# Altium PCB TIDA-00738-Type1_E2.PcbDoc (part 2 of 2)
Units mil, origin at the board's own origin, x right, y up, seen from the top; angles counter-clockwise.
Board outline 4723.41 x 3650 mil, 4 copper layers (Top Layer, GND, PWR, Bottom Layer), stack 79.834 mil thick; 251 components, 112 nets, 616 pads, 221 vias.
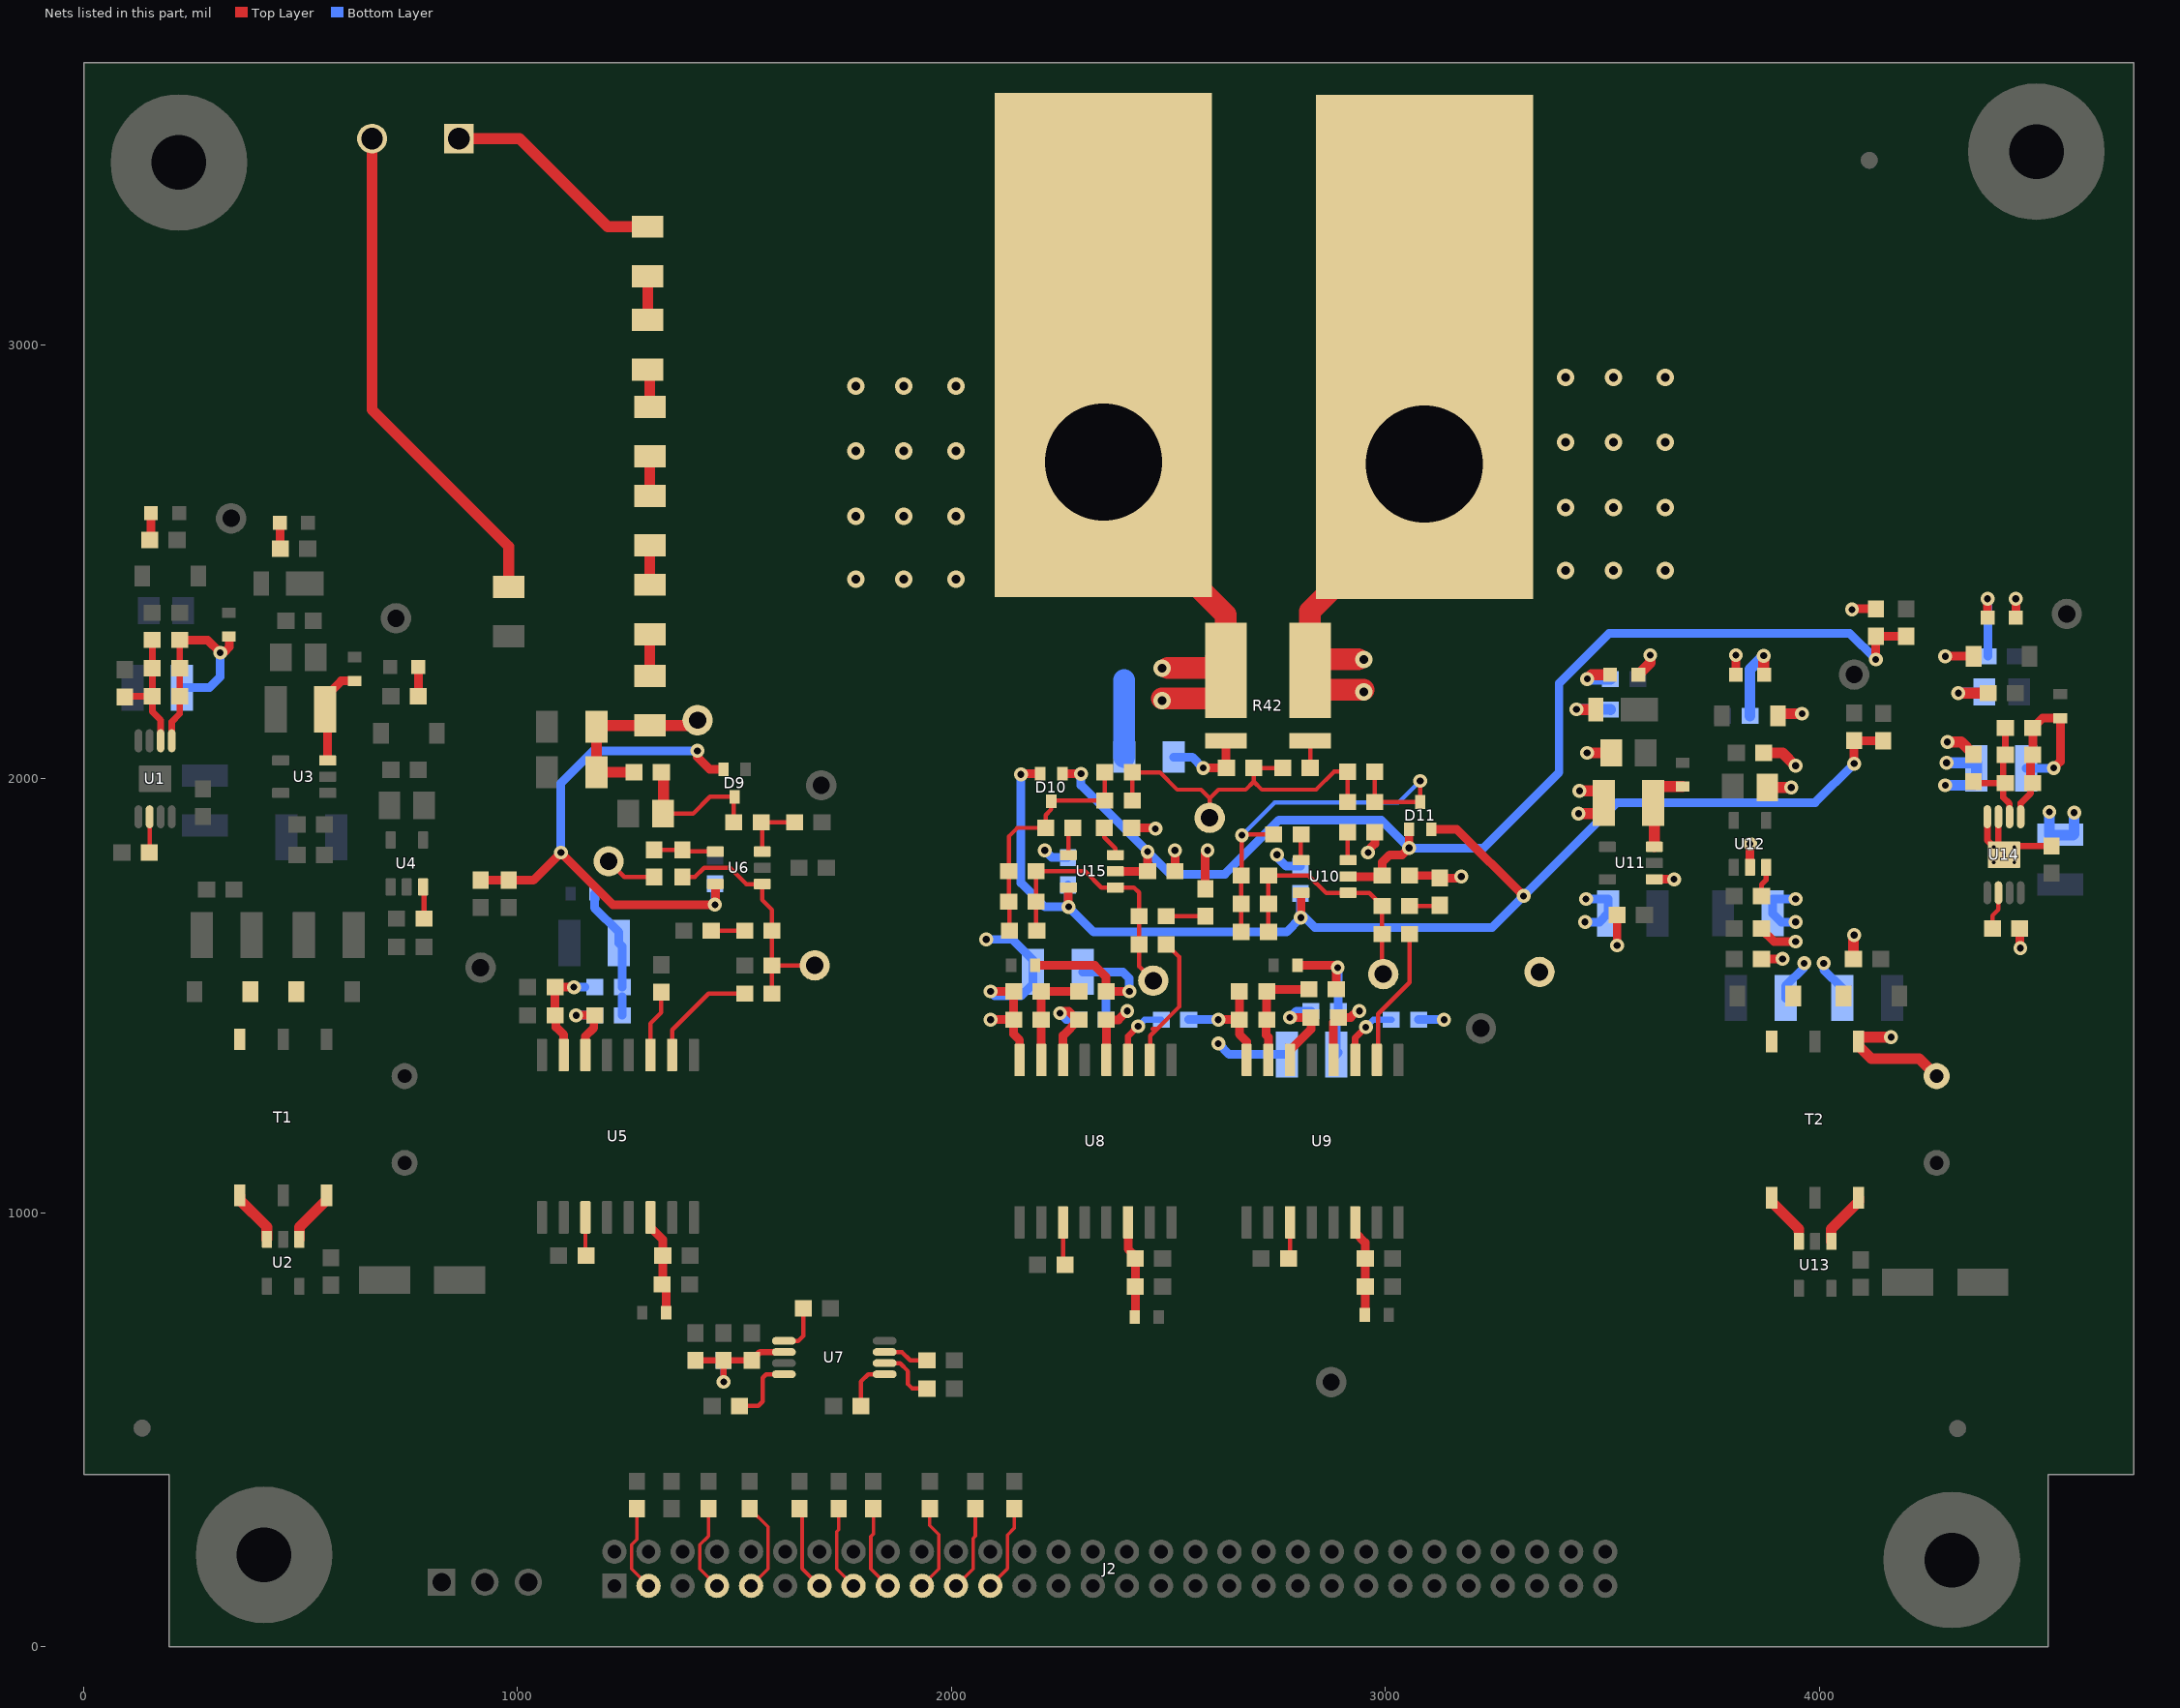
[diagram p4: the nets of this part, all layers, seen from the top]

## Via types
v1: diameter 32, hole 16, Top Layer to Bottom Layer, tented both sides, 183 vias
v2: diameter 40, hole 20, Top Layer to Bottom Layer, tented both sides, 28 vias
v3: diameter 19.68, hole 7.87, Top Layer to Bottom Layer, tented both sides, 10 vias

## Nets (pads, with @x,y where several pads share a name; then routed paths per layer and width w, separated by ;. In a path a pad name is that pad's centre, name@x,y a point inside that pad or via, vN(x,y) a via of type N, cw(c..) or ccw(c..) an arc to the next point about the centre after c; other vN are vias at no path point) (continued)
GND_USH: C30.2 C31.2 C32.2 C33.2 C36.1 C38.2 C39.2 C40.2 C41.2 C42.1 C46.2 C49.1 C50.1 C51.2 C52.1 C53.2 C54.2 C55.2 C56.1 C59.2 C60.2 C61.1 C63.2 C64.1 C65.1 C66.1 C67.1 C68.2 C69.1 C70.1 C71.2 C72.1 C73.1 C83.1 C84.1 D12.2 D13.1 D14.1 D15.2 D18.2 D19.1 R38.1 R42.2A R45.1 R50.1 R55.1 R57.2 R58.1 R79.1 T2.4 TP13.1 U8.4 U8.8 U9.4 U9.8 U11.1 U12.2 U14.3 U14.4 U14.9 | length 4972.9
  Top Layer w15: U14.4@4386.93,1912.6 4386.93,1858.07 4420,1825 v3(4425.31,1825) 4445.31,1845 4534.49,1845 C63.2@4535,1845.51 ; U14.9@4412.52,1842.72 U14.3@4412.52,1912.6
  Top Layer w20: v1(2090,1445) C31.2@2143.5,1445 ; v1(2090,1510) C30.2@2143.5,1510 C31.2@2143.5,1445 ; U8.8@2157,1352.01 2157,1398 2143.5,1411.5 C31.2@2143.5,1445 ; U8.4@2357.32,1351.69 U8.4@2357,1352.01 2357,1444.5 2384.5,1444.5 v1(2405,1465) ; R38.1@2415.02,1886.93 2468.07,1886.93 v1(2470,1885) ; C84.1@2515.02,1786.93 v1(2515,1835) ; v1(2580,2025) C40.2@2633.5,2025 2632,2026.5 R42.2A@2632,2087.5 ; C32.2@2585,1746.5 2585,1830 v1(2590,1835) ; v1(2615,1445) C39.2@2663.5,1445 ; C38.2@2663.5,1510 C39.2@2663.5,1445 ; U9.8@2680.32,1325 U9.8@2680.32,1352.01 2680.32,1394.68 2663.5,1411.5 C39.2@2663.5,1445 ; U9.4@2880.32,1352.01 2880.32,1438.82 C41.2@2891.5,1450 2920,1450 v1@2935,1465 ; v1(2960,1830) 2955,1830 2975.47,1850.47 R45.1@2975.47,1877.13 ; C36.1@3055.47,1777.13 3119.27,1777.13 C46.2@3124.97,1771.42 3171.42,1771.42 v1(3175,1775) ; v1@3460,1720 3462.09,1722.09 v1(3462.09,1722.91) ; v1(3533.82,1616.18) C51.2@3533.82,1685.98 ; U11.1@3619.45,1768.58 v1(3665,1768.58) ; D14.1@3807.52,2240 v1(3807.52,2285) ; U12.2@3840,1795.87 v1(3840,1850) ; C54.2@3866.5,1585 v1(3915,1585) ; C53.2@3866.5,1655 3866.5,1653.5 3895,1625 v1(3945,1625) ; v1(4075,2390) 4076.5,2391.5 R79.1@4130,2391.5 ; v1(4290.02,2282.27) D19.1@4355.55,2282.27 ; D18.2@4452.5,2371.28 v1(4452.54,2414.79) ; C61.1@4461.5,1655 4461.5,1611.5 v1(4462.99,1610)
  Top Layer w25: v1(3440,2160) 3440.31,2159.68 D12.2@3484.8,2159.68 ; v1(3445,1920) 3495,1920 3502.91,1927.91 C49.1@3502.91,1944.68 3502.91,1972.09 v1(3447.09,1972.09) ; v1(3464.69,2059.68) C50.1@3520,2059.68 ; D13.1@3582.48,2239.68 3610,2267.2 v1(3610,2285) ; C55.2@3871.5,2060 3915,2060 v1(3945,2030) ; C52.1@3890,1970 C52.1@3880,1980 v1(3935,1980) ; D15.2@3909.47,2145 3914.47,2150 v1(3960,2150) ; C56.1@4077.52,1585 C56.1@4078.5,1585 4078.5,1638.5 v1(4080,1640) ; v1(4165,1404.84) 4100,1404.84 T2.4@4090,1394.84 4090,1385 4120,1355 4230,1355 C59.2@4270,1315 ; v1(4293.02,2036.98) v1@4295,2035 ; v1(4295,2085) 4326.5,2085 R50.1@4355,2056.5 ; v1(4320.02,2197.27) C60.2@4388.52,2197.27
  Bottom Layer w20: v1(2080,1630) 2140,1630 2187.91,1582.09 C73.1@2187.91,1555 2187.91,1527.91 2160,1500 2100,1500 v1(2090,1510) ; v1(2215,1835) 2231.57,1818.43 C83.1@2268.53,1818.43 ; v1(2405,1465) v1@2410,1465 ; R57.2@2512.09,2050 2555,2050 v1(2580,2025) ; R58.1@2546.5,1445 v1(2615,1445) ; v1(2615,1390) 2640,1365 C72.1@2772.91,1365 ; v1(2750,1825) 2750,1820 2771.38,1798.62 C42.1@2803.97,1798.62 ; R55.1@3076.5,1445 v1(3135,1445) ; v1(3460,1670) 3493.23,1670 C70.1@3512.91,1689.68 3512.91,1722.91 v1(3462.09,1722.91) ; C68.2@3922.09,1495 3922.09,1522.61 3965,1565.52 v1(3965,1575) ; v1(3945,1670) 3912.09,1670 C69.1@3892.09,1690 3892.09,1722.91 v1(3945,1722.91) ; v1(4010,1575) 4010,1560 4052.91,1517.09 C67.1@4052.91,1495
  Bottom Layer w25: v1(3440,2160) 3518.19,2160 C71.2@3518.5,2159.68 ; v1(4290,1985) 4353.5,1985 4361.98,1993.48 C65.1@4361.98,2024.02 4361.98,2036.98 v1(4293.02,2036.98) ; v1(4320.02,2197.27) 4379.03,2197.27 C66.1@4380.02,2196.28 ; v1(4530,1923.86) 4530,1870 4583.86,1870 4586.93,1873.07 v1(4586.93,1921.93)
  other v1: 2940,1465
  other v3: 4401.69,1807.28 4448.94,1807.28 4401.69,1842.72 4448.94,1842.72
NetC1_2: C1.2 U1.6 | length 82.7
  Top Layer w10: C1.2@151.5,1830 152.2,1830.71 U1.6@152.2,1912.4
NetC3_1: C3.1 R1.2 R3.1 R77.1 U1.2 | length 304.5
  Top Layer w15: R1.2@95,2188.5 96.5,2190 R3.1@158.5,2190 ; C3.1@158.5,2320 R77.1@158.5,2255 R3.1@158.5,2190 ; U1.2@177.8,2087.6 177.8,2135.2 158.5,2154.5 R3.1@158.5,2190
NetC3_2: C3.2 C81.2 L1.1 R3.2 R77.2 U1.1 | length 534
  Top Layer w15: U1.1@203.39,2087.6 203.39,2131.39 221.5,2149.5 R3.2@221.5,2190 R77.2@221.5,2255 221.5,2307.5 C3.2@226.5,2312.5
  Top Layer w20: C3.2@221.5,2320 285.5,2320 v1(315,2290.5) ; v1@325,2292.5 336,2303.5 L1.1@336,2327.94
  Bottom Layer w20: C81.2@227.09,2210 290,2210 315,2235 v1(315,2290.5)
NetC7_2: C7.2 L2.1 U3.3 | length 232
  Top Layer w20: U3.3@562.61,2042.21 562.61,2154.48 C7.2@557.09,2160 557.09,2188.81 593.72,2225.44 L2.1@625,2225.44
NetC19_1: C19.1 C20.1 R60.2 U5.7 | length 234.1
  Top Layer w20: U5.7@1106.5,1363.5 1106.5,1410.24 1089,1427.73 1089,1452.5 C20.1@1086.5,1455 C19.1@1086.5,1520 v1(1130,1520)
  Bottom Layer w20: v1(1130,1520) 1155.82,1520
NetC21_1: C21.1 R61.2 U5.6 | length 187.6
  Top Layer w20: v1(1135,1455) C21.1@1178.5,1455 1176,1452.5 1176,1426 1156.5,1406.5 U5.6@1156.5,1363.5
  Bottom Layer w20: v1(1135,1455) R61.2@1178.5,1455
NetC22_2: C22.2 D9.3 R71.2 R81.1 | length 333.6
  Top Layer w10: C22.2@1335,1920 1405,1920 1443.5,1958.5 D9.3@1500,1958.5 1498.5,1957.01 R81.1@1498.5,1900
  Top Layer w25: C22.2@1336.5,1921.5 R71.2@1336.5,2015
NetC24_2: C24.2 C25.2 L5.1 U5.14 | length 235.7
  Top Layer w20: U5.14@1306.5,989.49 1306.5,966.5 1335,937.99 C25.2@1335,901.5 1335,836.5 C24.2@1333.5,835 1342.56,825.95 L5.1@1342.56,770
NetC26_1: C26.1 C27.1 C74.1 L6.2 U7.6 | length 288.2
  Top Layer w15: L6.2@1410,659.96 C26.1@1475,659.96 ; v1(1475,610.46) C26.1@1475,659.96 ; U7.6@1613.86,679.25 1559.29,679.25 C27.1@1540,659.96 C26.1@1475,659.96
  Bottom Layer w15: v1(1475,610.46) 1475,637.28
NetC28_1: C28.1 R19.1 | length 77
  Top Layer w10: C28.1@1446.5,1650 R19.1@1523.5,1650
NetC30_1: C30.1 C31.1 R35.2 U8.7 | length 245.2
  Top Layer w20: U8.7@2207,1352.01 2207,1444.5 C31.1@2206.5,1445 C30.1@2206.5,1510 R35.2@2293.5,1510
NetC32_1: C32.1 R36.1 | length 92.2
  Top Layer w10: R36.1@2495.02,1683.54 2495.06,1683.5 C32.1@2585,1683.5 C32.1@2583.43,1681.93
NetC33_1: C33.1 R59.2 U8.6 | length 226.9
  Top Layer w10: U8.6@2257,1339.69 U8.6@2257,1352.01
  Top Layer w20: v1(2250,1460) 2250,1465 2270,1465 2290,1445 C33.1@2293.5,1445 2257,1408.5 U8.6@2257,1352.01
  Bottom Layer w20: v1(2250,1460) 2265,1445 R59.2@2293.5,1445
NetC34_2: C34.2 C35.2 L9.1 U8.14 | length 207.5
  Top Layer w20: U8.14@2407,965.68 2407,917 C34.2@2423.5,900.5 ; L9.1@2422.44,760 2423.5,761.06 C35.2@2423.5,830 C34.2@2423.5,895
NetC37_1: C37.1 R36.2 R40.2 R66.2 R68.1 TP15.1 U15.1 | length 611.5
  Top Layer w10: C37.1@2196.5,1650 2195.02,1651.47 R40.2@2195.02,1716.93 R66.2@2195.02,1786.93 2308.07,1786.93 2345.47,1749.53 U15.1@2377.66,1749.53 2420.47,1749.53 2432.03,1737.97 R36.2@2432.03,1683.54 R68.1@2432.03,1618.54 2432.03,1567.97 TP15.1@2465,1535
NetC37_2: C37.2 D10.3 R37.2 R39.1 R40.1 R66.1 R67.2 | length 567
  Top Layer w10: C37.2@2133.5,1650 2133.5,1715.45 R40.1@2132.03,1716.93 R66.1@2132.03,1786.93 2132.03,1867.03 2151.93,1886.93 R39.1@2217.03,1886.93 2217.03,1916.7 2230,1929.67 D10.3@2230,1948.5 2231.5,1950 R67.2@2353.5,1950 R37.2@2353.5,2015
NetC38_1: C38.1 C39.1 R43.2 U9.7 | length 267
  Top Layer w20: U9.7@2730.32,1352.01 2730.32,1404.68 2725,1410 2725,1443.5 C39.1@2726.5,1445 C38.1@2726.5,1510 2731.5,1515 R43.2@2823.5,1515 R43.2@2818.5,1510
NetC41_1: C41.1 R56.2 U9.6 | length 221.2
  Top Layer w20: v1(2780,1450) C41.1@2828.5,1450 2828.5,1422.87 2780.32,1374.68 U9.6@2780.32,1352.01
  Bottom Layer w20: v1(2780,1450) 2795,1465 R56.2@2828.5,1465
NetC43_2: C43.2 C44.2 L14.1 U9.14 | length 223
  Top Layer w20: U9.14@2930.32,977.99 2930.32,954.68 2953.5,931.5 C43.2@2953.5,895 C44.2@2953.5,830 2953.5,766.06 L14.1@2952.44,765
NetC45_1: C45.1 R47.2 R48.2 R63.2 R65.1 TP12.1 U10.1 | length 579.2
  Top Layer w10: R63.2@2730.47,1647.13 R47.2@2730.47,1712.13 C45.1@2730.47,1777.13 2822.87,1777.13 2863.35,1736.65 2962.95,1736.65 R48.2@2992.48,1707.13 R65.1@2992.48,1642.13 2992.48,1552.52 TP12.1@2995,1550
NetC45_2: C45.2 D11.3 R44.2 R46.1 R47.1 R63.1 R64.2 | length 987.5
  Top Layer w10: R63.1@2667.48,1647.13 R47.1@2667.48,1712.13 C45.2@2667.48,1777.13 2669.25,1778.9 v1(2669.25,1870) 2667.13,1872.13 R46.1@2742.48,1872.13 ; R44.2@2975.47,2016.46 R64.2@2975.47,1946.46 R64.2@2975.47,1946.46 D11.3@3080,1946.5 v1(3080,1995)
  Bottom Layer w10: v1(2669.25,1870) 2744.25,1945 3030,1945 v1(3080,1995)
NetC46_1: C46.1 R48.1 | length 70
  Top Layer w10: R48.1@3055.47,1707.13 3123.67,1707.13 C46.1@3124.97,1708.43
NetC49_2: C49.2 L15.1 U11.3 | length 152.2
  Top Layer w25: C49.2@3617.09,1944.68 3619.45,1942.32 U11.3@3619.45,1843.39 ; C49.2@3635.07,1982.13 L15.1@3685,1982.13
NetC61_2: C61.2 U14.6 | length 88.2
  Top Layer w10: C61.2@4398.5,1655 4398.5,1684.7 4412.52,1698.72 U14.6@4412.52,1737.4
NetC62_1: C62.1 R50.2 R51.1 R69.1 U14.2 | length 285.7
  Top Layer w15: R50.2@4355,1993.5 4358.5,1990 R51.1@4423.5,1990 ; R69.1@4423.5,2060 R51.1@4423.5,1990 ; R69.1@4428.5,2055 C62.1@4428.5,2117.25 ; U14.2@4438.11,1912.6 4438.11,1942.35 4423.5,1956.95 R51.1@4423.5,1990
NetC62_2: C62.2 C65.2 L16.1 R51.2 R69.2 U14.1 | length 477.1
  Top Layer w15: U14.1@4463.7,1912.6 4463.7,1943.7 4486.5,1966.5 R51.2@4486.5,1990
  Top Layer w20: R51.2@4486.5,1990 R69.2@4486.5,2060 ; R69.2@4491.5,2055 4491.5,2117.25 4513.95,2139.71 L16.1@4555.02,2139.71 4555.02,2040.02 v1(4540,2025)
  Bottom Layer w20: C65.2@4476.16,2024.02 4539.02,2024.02 v1(4540,2025)
NetC72_2: C72.2 L11.1 R43.1 R56.1 | length 354.6
  Top Layer w20: L11.1@2797.56,1570 2885,1570 v1(2890,1565) 2886.5,1561.5 R43.1@2886.5,1515
  Bottom Layer w20: v1(2890,1565) 2891.5,1563.5 R56.1@2891.5,1465 2887.09,1460.59 C72.2@2887.09,1365 C72.2@2891.5,1369.41
NetC73_2: C73.2 L8.1 R35.1 R59.1 | length 516.6
  Top Layer w20: L8.1@2192.56,1570 2330,1570 2356.5,1543.5 R35.1@2356.5,1510 v1(2410,1510)
  Bottom Layer w20: C73.2@2302.09,1555 2395,1555 2410,1540 v1(2410,1510) 2370,1510 2356.5,1496.5 R59.1@2356.5,1445
NetC76_2: C76.2 L17.1 R60.1 R61.1 | length 284.8
  Bottom Layer w20: L17.1@1177.56,1735 1177.56,1702.44 1233.58,1646.42 C76.2@1233.58,1621.5 1241.5,1613.58 R60.1@1241.5,1520 ; R61.1@1241.5,1455 1241.5,1498.3
NetD1_1: D1.1 R2.1 | length 63.2
  Top Layer w20: R2.1@152.5,2550.5 155.52,2553.52 D1.1@155.52,2612.5
NetD3_1: D3.1 D6.2 T1.6
NetD5_2: D5.2 R4.1 | length 62.5
  Top Layer w20: D5.2@447.52,2590 453.5,2584.02 R4.1@453.5,2530
NetD7_2: D7.2 R5.1 | length 68
  Top Layer w20: R5.1@771.5,2190 D7.2@771.48,2258
NetD13_2: D13.2 R54.1 | length 110.2
  Top Layer w25: v1(3465,2230) 3474.69,2239.68 D13.2@3517.52,2239.68
  Bottom Layer w25: v1(3465,2230) 3465.31,2229.68 R54.1@3518.5,2229.68
NetD14_2: D14.2 R53.1 | length 196.7
  Top Layer w25: v1(3871.5,2283.5) 3871.5,2243.98 3870,2242.48 D14.2@3872.48,2240
  Bottom Layer w25: R53.1@3840,2145 3840,2252.01 v1(3871.5,2283.5)
NetD16_2: D16.2 D17.1 T2.6
NetD18_1: D18.1 R52.1 | length 176.4
  Top Layer w20: D18.1@4387.54,2371.28 v1(4387.54,2414.75)
  Bottom Layer w20: v1(4387.54,2414.75) 4388.52,2413.76 R52.1@4388.52,2282.27
NetJ1_1: J1.1 R7.1 | length 519
  Top Layer w25: J1.1@865,3475 1005,3475 1207.91,3272.09 R7.1@1300,3272.09
NetJ2_3: J2.3 R12.2 | length 199
  Top Layer w8: R12.2@1275,318.5 1275,247.52 1263.01,235.52 1263.01,179.63 J2.3@1302.01,140.63
NetJ2_7: J2.7 R21.2 | length 202.1
  Top Layer w8: R21.2@1440,318.5 1440,255.04 1420.49,235.52 1420.49,179.63 J2.7@1459.49,140.63
NetJ2_9: J2.9 R23.2 | length 211.5
  Top Layer w8: R23.2@1535,318.5 1577.23,276.28 1577.23,179.63 J2.9@1538.23,140.63
NetJ2_13: J2.13 R24.2 | length 196.8
  Top Layer w8: R24.2@1650,318.5 1655.97,312.54 1655.97,180.37 J2.13@1695.71,140.63
NetJ2_15: J2.15 R27.2 | length 195.9
  Top Layer w8: R27.2@1740,318.5 1740,270 1735.45,265.45 1735.45,179.63 J2.15@1774.45,140.63
NetJ2_17: J2.17 R28.2 | length 196.4
  Top Layer w8: R28.2@1820,318.5 1820,260 1814.19,254.19 1814.19,179.63 J2.17@1853.19,140.63
NetJ2_19: J2.19 R31.2 | length 202.7
  Top Layer w8: J2.19@1931.93,140.63 1970.93,179.63 1970.93,259.07 1950,280 R31.2@1950,318.5
NetJ2_21: J2.21 R32.2 | length 196.2
  Top Layer w8: J2.21@2010.67,140.63 2049.67,179.63 2049.67,250 2055,255.33 R32.2@2055,318.5
NetJ2_23: J2.23 R34.2 | length 200.9
  Top Layer w8: J2.23@2089.41,140.63 2129.15,180.37 2129.15,257.89 2145,273.74 R34.2@2145,318.5
NetJ4_1: J4.1 R42.2 R57.1 | length 1041.7
  Top Layer w50: J4.1@2350,2730 2350,2660 2632,2378 R42.2@2632,2250 ; v2@2485,2185 R42.2@2615,2185 ; v2@2498,2255 2610,2255 R42.2@2610,2280
  Bottom Layer w50: R57.1@2397.91,2050 2397.91,2227.91
  other v2: 2485,2180 2485,2255 1780,2460 1890,2460 2010,2460 1780,2605 1890,2605 2010,2605 1780,2755 1890,2755 2010,2755 1780,2905 1890,2905 2010,2905
NetJ5_1: J5.1 R42.1 | length 851.4
  Top Layer w50: R42.1@2820,2205 v2@2950,2205 ; R42.1@2825,2300 2825,2275 v2@2937,2275 ; R42.1@2826,2250 2826,2386 2850,2410 3090,2650 J5.1@3090,2725
  other v2: 2950,2200 2950,2275 3415,2480 3525,2480 3645,2480 3415,2625 3525,2625 3645,2625 3415,2775 3525,2775 3645,2775 3415,2925 3525,2925 3645,2925
NetR6_1: R6.1 U4.3 | length 73.7
  Top Layer w12: U4.3@782.4,1750.87 784.5,1748.77 R6.1@784.5,1678
NetR7_2: R7.2 R13.1 | length 75.2
  Top Layer w25: R13.1@1297.91,3055 R13.1@1300,3057.09 1300,3129.32
NetR8_2: R8.2 R9.2 R17.2 R71.1 TP6.1 | length 430.5
  Top Layer w25: R71.1@1268.5,2015 R9.2@1182.09,2015 R8.2@1182.09,2120 1185,2122.91 R17.2@1305,2122.91 1402.91,2122.91 TP6.1@1415,2135
NetR10_1: R10.1 U5.11 | length 88.6
  Top Layer w10: R10.1@1151.5,902.99 1151.5,911.5 1156.5,916.5 U5.11@1156.5,989.49
NetR11_2: R11.2 U5.3 | length 155.4
  Top Layer w10: U5.3@1306.5,1363.5 1306.5,1436.5 1331.5,1461.5 R11.2@1331.5,1508.5
NetR13_2: R13.2 R14.1 | length 87.9
  Top Layer w25: R13.2@1300,2942.91 1305,2937.91 R14.1@1305,2857.09
NetR14_2: R14.2 R15.1 | length 90.8
  Top Layer w25: R15.1@1305,2652.09 R14.2@1305,2742.91
NetR15_2: R15.2 R16.1 | length 90.8
  Top Layer w25: R16.1@1305,2447.09 R15.2@1305,2537.91
NetR16_2: R16.2 R17.1 | length 95.8
  Top Layer w25: R17.1@1305,2237.09 R16.2@1305,2332.91
NetR19_2: R19.2 R20.2 R70.2 R80.1 TP7.1 U6.1 | length 568.9
  Top Layer w10: R70.2@1380,1773.5 1408.5,1773.5 1430,1795 1490,1795 1527.4,1757.6 U6.1@1564.13,1757.6 1564.13,1720.87 1586.5,1698.5 R19.2@1586.5,1650 R20.2@1586.5,1570 ; R80.1@1586.5,1505 R20.2@1586.5,1570 ; TP7.1@1685,1570 R20.2@1586.5,1570
NetR22_2: R22.2 U7.8 | length 168.2
  Top Layer w10: R22.2@1511.5,555 1555,555 1565,565 1565,620 1573.07,628.07 U7.8@1613.86,628.07 U7.8@1611.5,625.71
NetR25_2: R25.2 U7.5 | length 113
  Top Layer w10: U7.5@1613.86,704.84 1646.94,704.84 1658.5,716.4 R25.2@1658.5,780
NetR26_1: R26.1 U7.1 | length 118
  Top Layer w10: R26.1@1791.5,555 1791.5,611.5 1808.07,628.07 U7.1@1846.14,628.07
NetR29_2: R29.2 U7.3 | length 105.3
  Top Layer w10: U7.3@1846.14,679.25 1885.75,679.25 1905,660 R29.2@1943.5,660
NetR30_1: R30.1 U7.2 | length 139.2
  Top Layer w10: U7.2@1846.14,653.66 1881.34,653.66 1900,635 1900,605 1910,595 R30.1@1943.5,595
NetR33_1: R33.1 U8.11 | length 87.3
  Top Layer w10: R33.1@2255,891.5 2257,893.5 U8.11@2257,977.99
NetR38_2: R38.2 U15.3 | length 83.2
  Top Layer w10: R38.2@2345,1879.9 R38.2@2352.03,1886.93 2352.03,1864.94 2377.66,1839.31 U15.3@2377.66,1824.33
NetR39_2: R39.2 U15.4 | length 67
  Top Layer w10: U15.4@2269.39,1824.33 2269.39,1876.3 R39.2@2280.02,1886.93
NetR41_1: R41.1 U9.11 | length 86.5
  Top Layer w10: R41.1@2780.32,891.5 U9.11@2780.32,977.99
NetR42_1A: R42.1A R74.1 | length 62.7
  Top Layer w10: R42.1A@2826,2087.5 2826.5,2087 R74.1@2826.5,2025
NetR45_2: R45.2 U10.3 | length 65.9
  Top Layer w10: R45.2@2912.48,1877.13 2913.11,1876.5 U10.3@2913.11,1811.46
NetR46_2: R46.2 U10.4 | length 60.9
  Top Layer w10: U10.4@2804.84,1811.46 2804.84,1871.5 R46.2@2805.47,1872.13
NetR49_1: R49.1 U12.3 | length 75.4
  Top Layer w12: R49.1@3866.5,1730 3866.5,1756.5 3877.4,1767.4 U12.3@3877.4,1800.87
NetR55_2: R55.2 U9.3 | length 151.8
  Top Layer w15: U9.3@2930.32,1352.01 2930.32,1403.31 v1(2955,1427.99)
  Bottom Layer w15: v1(2955,1427.99) 2972.01,1445 R55.2@3013.5,1445
NetR58_2: R58.2 U8.3 | length 147.2
  Top Layer w15: U8.3@2407,1352.01 2407,1407 v1(2430,1430)
  Bottom Layer w15: v1(2430,1430) 2445,1445 R58.2@2483.5,1445
NetR65_2: R65.2 U9.2 | length 321.2
  Top Layer w10: U9.2@2980.32,1352.01 2983,1354.69 2983,1458 3055.47,1530.47 R65.2@3055.47,1642.13
NetR68_2: R68.2 U8.2 | length 317.3
  Top Layer w10: U8.2@2457,1352.01 2458,1353.01 2458,1408 2474,1424 ; 2464.03,1424 2474,1424 ; R68.2@2495.02,1618.54 2496.01,1618.54 2524.55,1590 2524.55,1474.55 2474,1424
NetR70_1: R70.1 R82.2 U6.4 | length 142.6
  Top Layer w10: R82.2@1315,1836.5 R70.1@1380,1836.5 1384.09,1832.4 U6.4@1455.87,1832.4
NetR80_2: R80.2 U5.2 | length 259.6
  Top Layer w10: U5.2@1356.5,1363.5 1356.5,1421.5 1440,1505 R80.2@1523.5,1505
NetR81_2: R81.2 R83.2 U6.3 | length 145.7
  Top Layer w10: U6.3@1564.13,1832.4 1564.13,1897.36 R81.2@1561.5,1900 R83.2@1638.5,1900
NetR82_1: R82.1 TP14.1 | length 120.1
  Top Layer w10: TP14.1@1210,1810 1246.5,1773.5 R82.1@1315,1773.5
NetT1_1: T1.1 U2.3 | length 126.8
  Top Layer w25: T1.1@360,1040 360,1030 422.6,967.4 U2.3@422.6,939.13
NetT1_3: T1.3 U2.1 | length 126.8
  Top Layer w25: U2.1@497.4,939.13 497.4,967.4 560,1030 T1.3@560,1040
NetT2_1: T2.1 U13.3 | length 103.9
  Top Layer w25: T2.1@3890,1035 3890,1025 3952.6,962.4 3952.6,956.98
NetT2_3: T2.3 U13.1 | length 126.8
  Top Layer w25: U13.1@4027.4,934.13 4027.4,962.4 4090,1025 T2.3@4090,1035
NEUTRAL: J1.2 R62.1 | length 1163.4
  Top Layer w25: J1.2@665,3475 665,2850 980,2535 R62.1@980,2442.09
SHUNT_H: C40.1 R37.1 R44.1 R64.1 R67.1 R74.2 TP9.1 | length 840.1
  Top Layer w10: R67.1@2416.5,1950 R37.1@2416.5,2015 2480,2015 2520,1975 2575,1975 2595,1955 ; TP9.1@2595,1910 2595,1955 ; R74.2@2763.5,2025 C40.1@2696.5,2025 2696.5,1993.5 ; R64.1@2912.48,1946.46 R44.1@2912.48,2016.46 2881.46,2016.46 2840,1975 2715,1975 2696.5,1993.5 ; 2595,1955 2615,1975 2677.99,1975 2696.5,1993.5
VAN+: C42.2 C83.2 D10.2 D11.2 R75.2 R76.2 U10.5 U15.5 | length 3035.4
  Top Layer w20: v1(2160,2010) 2161.5,2011.5 D10.2@2204.41,2011.5 ; U15.5@2269.39,1749.53 2269.39,1705.61 v1(2270,1705) ; v1(2805,1680) 2805.87,1680.87 U10.5@2805.87,1737.6 ; D11.2@3105.59,1883.5 3164.83,1883.5 v1(3318.33,1730) v1@3318.5,1730.17 ; v1(4080,2035) R75.2@4080,2088.5 4081,2087.5 R76.2@4147,2087.5 R76.2@4146,2088.5
  Bottom Layer w20: v1(2160,2010) 2160,1760 2215,1705 v1(2270,1705) ; C83.2@2268.53,1755.43 2268.53,1706.47 v1(2270,1705) ; v1@2803.97,1691.03 C42.2@2803.97,1735.63 ; v1(2805,1680) 2772.16,1647.16 2327.84,1647.16 v1(2270,1705) ; v1@2810,1685 2837.5,1657.5 3245.84,1657.5 v1(3318.33,1730) 3533.33,1945 3990,1945 v1(4080,2035)
VAN-: C36.2 C84.2 D10.1 D11.1 R78.2 R79.2 U10.2 U15.2 | length 2886.2
  Top Layer w20: D10.1@2255.59,2011.5 v1(2298.5,2011.5) ; U15.2@2377.66,1786.93 C84.2@2452.03,1786.93 v1(2452.03,1832.03) ; U10.2@2913.11,1774.05 2989.41,1774.05 C36.2@2992.48,1777.13 2992.48,1807.48 3010,1825 3038.82,1825 v1(3054.41,1840.59) D11.1@3054.41,1883.5 ; v1(4130,2275) R79.2@4130,2328.5 R78.2@4200,2328.5
  Bottom Layer w20: v1(2298.5,2011.5) 2298.5,1985.55 v1(2452.03,1832.03) 2504.06,1780 2630,1780 2755,1905 2990,1905 v1(3054.41,1840.59) 3225.59,1840.59 3400,2015 3400,2220 3515,2335 4070,2335 v1(4130,2275)
VANP+: C29.2 D9.2 R72.2 R73.2 U6.5 | length 1280.9
  Top Layer w20: R72.2@915,1766.5 R73.2@980,1766.5 1036.5,1766.5 v1(1100,1830) 1220,1710 v1(1455,1710) 1455.87,1710.87 U6.5@1455.87,1757.6 ; v1(1414.41,2064.41) 1414.41,2050.59 1443.5,2021.5 D9.2@1474.41,2021.5
  Bottom Layer w20: v1(1100,1830) 1100,1990 1174.41,2064.41 v1(1414.41,2064.41) ; v1(1455,1710) 1455,1735.82
pads on no net: FID1.1 FID2.1 FID3.1 FID4.1 FID5.1 FID6.1 H1.1 H2.1 H3.1 H4.1 J2.4 J2.6 J2.8 J2.10 J2.11 J2.12 J2.14 J2.16 J2.18 J2.20 J2.24 J2.25 J2.26 J2.27 J2.28 J2.29 J2.30 J2.31 J2.32 J2.33 J2.34 J2.35 J2.36 J2.37 J2.38 J2.41 J2.42 J2.43 J2.44 J2.45 J2.46 J2.47 J2.48 J2.49 J2.50 J2.51 J2.52 J2.53 J2.54 J2.55 J2.56 J2.57 J2.58 R24.1 R27.1 R32.1 R34.1 T1.5 T2.5 U1.7 U3.4 U3.5 U4.4 U5.1 U5.5 U5.10 U5.12 U5.15 U7.7 U8.1 U8.5 U8.10 U8.12 U8.15 U9.1 U9.5 U9.10 U9.12 U9.15 U11.4 U11.5 U12.4 U14.7

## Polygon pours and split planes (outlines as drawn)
+6V_PH on Top Layer "Top Layer-No Net" (solid, pour order 27): 720,1775 720,1720 740,1700 745,1695 745,1675 745,1490 730,1475 592.5,1475 580,1487.5 580,1730 575,1735 465,1735 405,1795 385,1815 385,1895 385,1920 395,1930 510,1930 515,1925 515,1795 520,1790 705,1790
-6V_PH on Top Layer "Top Layer-No Net" (solid, pour order 21): 270,1480 210,1480 200,1490 200,1925 210,1935 325,1935 335,1925 335,1805 300,1770 300,1635 300,1490 290,1480
NetD3_1 on Top Layer "Top Layer-No Net" (solid, remove dead copper, pour order 25): 360,1535 370,1545 500,1545 505,1540 505,1455 500,1450 395,1450 370,1425 370,1405 370,1380 365,1375 300,1375 295,1380 295,1420 360,1485
+6V_USH on Top Layer "Top Layer-No Net" (solid, remove dead copper, pour order 28): 3575,1720 3580,1725 3585,1730 3645,1730 3650,1730 3660,1740 3665,1745 3665,1790 3660,1795 3635,1795 3635,1815 3660,1815 3665,1820 3670,1825 3705,1825 3810,1825 3815,1820 3815,1778 3815,1775 3825,1765 3825,1690 3825,1575 3825,1470 3825,1450 3820,1445 3745,1445 3590,1445 3575,1460 3575,1720
NetD16_2 on Top Layer "Top Layer-No Net" (solid, remove dead copper, pour order 29): 3825,1375 3830,1370 3905,1370 3910,1375 3910,1415 3940,1445 4065,1445 4075,1455 4075,1535 4070,1540 3930,1540 3920,1530 3920,1485 3865,1430 3830,1430 3825,1425
-6V_USH on Top Layer "Top Layer-No Net" (solid, pour order 35): 4470,1770 4465,1765 4465,1710 4490,1710 4495,1705 4520,1680 4520,1670 4520,1595 4510,1585 4370,1585 4355,1600 4355,1750 4345,1760 4130,1760 4120,1750 4120,1555 4125,1550 4145,1550 4160,1535 4160,1470 4175,1455 4605,1455 4630,1480 4630,1790 4615,1805 4505,1805 4485,1785
NetJ4_1 on Top Layer "Bottom Layer-No Net 1" (solid, remove dead copper, pour order 20): 2600,2450 2600,2150 2590,2140 2585,2135 2450,2135 2370,2135 2360,2145 2360,2410 2350,2420 1755,2420 1735,2440 1735,2930 1755,2950 2095,2950 2105,2960 2105,3550 2120,3565 2585,3565 2595,3555
NetJ5_1 on Top Layer "Bottom Layer-No Net 1" (solid, remove dead copper, pour order 24): 2840,2470 2840,2145 2845,2140 3015,2140 3030,2155 3030,2399.29 3040.71,2410 3665,2410 3685,2430 3685,2980 3670,2995 3360,2995 3345,3010 3315,3040 3315,3265 3315,3545 3305,3555 2850,3555 2840,3545
GND_USH on GND "Top Layer-No Net" (solid, remove dead copper, pour order 32): 3945,1595 3950,1600 4000,1600 4015,1600 4020,1595 4025,1590 4025,1565 4025,1500 4025,1455 4050,1430 4170,1430 4185,1415 4185,1390 4185,1385 4175,1375 4170,1370 4050,1370 3960,1370 3945,1385 3945,1590
DGND on GND "Top Layer-No Net" (solid, remove dead copper, pour order 33): 50,825 50,950 75,975 325,975 535,975 710,1150 790,1150 915,1025 3750,1025 3800,975 4075,975 4250,1150 4475,1150 4650,975 4675,950 4675,800 4675,625 4650,600 4400,600 4175,600 4050,475 4000,425 4000,350 4000,75 3975,50 725,50 700,75 700,450 700,575 650,625 175,625 100,625 50,675
GND_USH on GND "Top Layer-No Net" (solid, remove dead copper, pour order 34): 2045,1980 2110,2045 3170,2045 3450,2325 3675,2325 3925,2325 4100,2500 4625,2500 4675,2450 4675,1775 4675,1475 4650,1450 4300,1450 4075,1450 4050,1475 4050,1570 4040,1580 3880,1580 3825,1525 3815,1515 3815,1450 3815,1440 3775,1400 3750,1375 3725,1350 3700,1325 2750,1325 2085,1325 2045,1365
GND_PH on GND "Top Layer-No Net" (solid, pour order 36): 695,1450 695,1385 685,1375 410,1375 400,1385 400,1685 405,1690 465,1690 470,1685 470,1465 480,1455 690,1455 695,1450
GND_PH on GND "Top Layer-No Net" (solid, pour order 23): 55,2635 55,2640 85,2670 515,2670 905,2280 1005,2280 1030,2255 1030,1970 1055,1945 1505,1945 1740,1945 1765,1920 1765,1345 1735,1315 935,1315 779.37,1470.63 594.37,1470.63 585,1480 585,1655 560,1680 290,1680 270,1660 270,1540 250,1520 90,1520 50,1560 50,2630
+3.3V_DVDD on PWR "Top Layer-No Net" (solid, remove dead copper, pour order 31): 800,75 3725,75 3750,100 3750,1000 3725,1025 850,1025 775,950 775,100
+5.0V_PH on PWR "Top Layer-No Net" (solid, remove dead copper, pour order 30): 475,2375 500,2400 675,2400 750,2400 775,2375 775,1898.49 884.66,1788.83 1745.99,1788.83 1765,1769.82 1765,1345 1745,1325 925,1325 475,1775
+5.0V_USH on PWR "Bottom Layer-No Net 1" (solid, remove dead copper, pour order 26): 2045,1617.97 2045,1365 2085,1325 3575,1325 4240,1990 4240,2287.28 4227.27,2300.02 4197.28,2330 3620,2330 3455,2330 3401.91,2276.91 3120,1995 2552.89,1995 2500,1942.11 2500,1850 2475,1825 2375,1825 2294.8,1744.8 2175,1625 2172.89,1622.89 2049.29,1622.89
NetJ4_1 on Bottom Layer "Bottom Layer-No Net 1" (solid, remove dead copper, pour order 19): 2600,2450 2600,2150 2590,2140 2585,2135 2450,2135 2370,2135 2360,2145 2360,2410 2350,2420 1755,2420 1735,2440 1735,2930 1755,2950 2095,2950 2105,2960 2105,3550 2120,3565 2585,3565 2595,3555
NetJ5_1 on Bottom Layer "Bottom Layer-No Net 1" (solid, remove dead copper, pour order 22): 2840,2470 2840,2145 2845,2140 3015,2140 3030,2155 3030,2399.29 3040.71,2410 3665,2410 3685,2430 3685,2980 3670,2995 3360,2995 3345,3010 3315,3040 3315,3265 3315,3545 3305,3555 2850,3555 2840,3545

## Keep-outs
Keep-Out Layer:
  lines w10: 25,421.7 220.15,421.7 221.85,420 221.85,25 4502,25 4502,393 4502,417 4506.7,421.7 4700,421.7 4700,3630 25,3630 25,421.7
  text ".Layer_Name" at 552,-833.49 h60

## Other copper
Top Layer:
  pour cut-out: 2917.5,2430 2912.5,2435 2777.5,2435 2777.5,2205 2797.5,2185 2907.5,2185 2917.5,2195
  pour cut-out: 2537.5,2430 2542.5,2435 2677.5,2435 2677.5,2205 2657.5,2185 2547.5,2185 2537.5,2195
  text ".Layer_Name" at 552,-833.49 h60
GND:
  text ".Layer_Name" at 552,-833.49 h60
PWR:
  text ".Layer_Name" at 544,-841.49 h60
Bottom Layer:
  text ".Layer_Name" at 552,-833.49 h60

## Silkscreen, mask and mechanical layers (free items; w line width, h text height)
Top Overlay:
  circle w6: c1605,1745 r9.37
  circle w6: c590,1940 r7.07
  circle w6: c1405,1420 r6.4
  circle w6: c535,938 r5
  circle w6: c3640,1730 r7.07
  circle w6: c2505,1410 r7.81
  circle w6: c1850,586 r8.06
  circle w6: c4500,1910 r5
  circle w6: c4060,960 r5
  circle w6: c3030,1405 r5
  circle w6: c203.39,2131.39 r9.19
  circle w10: c660,1750 r10
  circle w10: c2380,1710 r5
  circle w10: c2940,1705 r5
  circle w10: c3755,1800 r7.07
  lines w6: 638,785 658,785 ; 648,772 648,798 ; 660,1089 ccw(c740,1089) 820,1089 ; 660,1090 660,1340 cw(c740,1340) 820,1340 820,1090 ; 798,2259 813,2259 ; 812,2249 812,2269 ; 828,2258 829,2259 844,2259 ; 828,2264 828,2274 813,2259 ; 828,2269 828,2244 813,2259 ; 2295,2105 2215,2105 2215,2255 2300,2255 2315,2255 2315,2140 ; 2305,2040 2305,2060 2325,2060 ; 2310,1930 2310,1990 ; 2350,2055 2320,2085 2320,2115 ; 2361.97,1855 2366.97,1850 2405,1850 ; 2365,2060 2455,2060 2455,1905 ; 2615,1640 2620,1645 2630,1645 ; 2758.96,1684.93 2765.07,1684.93 2780,1670 2780,1655 2790,1645 ; 2870,1850 2870,2045 2890,2065 2970,2065 ; 2985,2055 3050,2120 ; 3015,1870 3015,2060 ; 3055,2140 3055,2245 3175,2245 3175,2100 3065,2100 ; 3125,1570 3105,1570 3095,1580 3095,1600 ; 4152,785 4172,785 ; 4162,772 4162,798 ; 4190,1090 ccw(c4270,1090) 4350,1090 ; 4190,1091 4190,1341 cw(c4270,1341) 4350,1341 4350,1091 ; 2320,2115 2310,2105 2330,2105 2320,2115 ; 3050,2120 3030,2120 3045,2105 3050,2100 3050,2120 ; 3095,1600 3085,1590 3105,1590 3095,1600 ; 3135,1500 3135,1640 3185,1640 3245,1640 3245,1500 3135,1500
  text "TIDA-00738-Type1-E2" at 3460,3090 h60
  text "HIGH VOLTAGE" at 724,2862 h40
  text ".Layer_Name" at 552,-833.49 h60
Bottom Overlay:
  text ".Layer_Name" at 552,-833.49 h60
Top Paste:
  text ".Layer_Name" at 552,-833.49 h60
Bottom Paste:
  text ".Layer_Name" at 552,-833.49 h60
Top Solder:
  rectangle: 1735,2425 2323.46,2950
  rectangle: 3150,2415 3685,2980
  text ".Layer_Name" at 552,-833.49 h60
  text ".Layer_Name" at 552,-833.49 h60
Bottom Solder:
  text ".Layer_Name" at 552,-833.49 h60
Drill Guide:
  text ".Layer_Name" at 552,-833.49 h60
M1 Board Outline:
  the board outline again, w10
M2 Board Dimensions:
  rectangle: -25.5,-260.5 99.5,-135.5
  rectangle: 99.5,-385.5 474.5,-260.5
  lines w7: -25.5,-260.5 974.5,-260.5 ; 99.5,-385.5 99.5,-135.5 ; 224.5,-385.5 224.5,-135.5 ; 474.5,-385.5 474.5,-135.5 ; 724.5,-385.5 724.5,-135.5 ; -25.5,-385.5 974.5,-385.5 974.5,-135.5 -25.5,-135.5 -25.5,-385.5
  lines w10: -25.5,-450.5 -25.5,-430.5 ; 34.5,-460.5 -25.5,-440.5 ; 34.5,-420.5 -25.5,-440.5 ; 198.58,-440.5 -25.5,-440.5 ; 750.42,-440.5 974.5,-440.5 ; 914.5,-460.5 974.5,-440.5 ; 914.5,-420.5 974.5,-440.5 ; 974.5,-450.5 974.5,-430.5
  text "1000 (mil)" at 208.58,-476.49 h60
M3 3D STEP Top:
  text ".Layer_Name" at 552,-833.49 h60
M4 3D STEP Bottom:
  text ".Layer_Name" at 552,-833.49 h60
M5 Assembly Top:
  circle w6: c3029.53,1360.47 r9.2
  circle w6: c2504.53,1360.47 r9.2
  circle w6: c1406.5,1363.5 r9.2
  circle w6: c360,1040 r10
  circle w6: c3890,1035 r10
  circle w6: c580,1967.4 r7.07
  circle w6: c4027.4,950 r10.14
  circle w6: c3641.4,1770 r6.4
  circle w6: c497.4,955 r5.83
  circle w6: c1525.59,2050 r7.07
  circle w6: c1580,1755 r7.07
  circle w6: c2395,1749.53 r6.75
  circle w6: c2255,2040 r7.07
  circle w6: c3054.41,1855 r5.03
  circle w10: c710,1735 r5
  circle w6: c2930,1736.65 r6.75
  circle w6: c3805,1779.53 r6.75
  lines w6: 140,2600 235,2600 235,2630 140,2630 ; 530,2575 435,2575 435,2605 530,2605 ; 690,2245 785,2245 785,2275 690,2275 ; 707,840 728,840 ; 718,828 718,853 ; 3596.03,2223.99 3501.03,2223.99 3501.03,2253.99 3596.03,2253.99 ; 3790,2225 3885,2225 3885,2255 3790,2255 ; 4145,847 4166,847 ; 4156,835 4156,860 ; 4375,2360 4470,2360 4470,2390 4375,2390 ; 310,1000.63 310,1441.57 610,1441.57 610,1000.63 310,1000.63 ; 1026.97,958.03 1431.97,958.03 1438.19,964.25 1438.19,1396.97 1026.97,1396.97 1026.97,958.03 ; 2125,955 2125,1393.94 2536.22,1393.94 2536.22,961.22 2530,955 2125,955 ; 2650,955 2650,1393.94 3061.22,1393.94 3061.22,961.22 3055,955 2650,955 ; 3840,995.63 4140,995.63 4140,1436.57 3840,1436.57 3840,995.63
  lines w10: -317,-905.17 6283,-905.17 ; -317,-701.83 6285,-701.83 ; -317,-498.5 -317,-1108.5 3688,-1108.5 6285,-1108.5 6285,-498.5 -316.5,-498.5 -316.5,-1108.5 1259,-1108.5 ; 140,2600 140,2630 ; 530,2575 530,2605 ; 690,2245 690,2275 ; 2148,-1108.5 2148,-498.5 ; 3415,-701.83 3415,-498.5 ; 3596.03,2223.99 3596.03,2253.99 ; 3790,2225 3790,2255 ; 4255,-701.83 4255,-498.5 ; 4375,2360 4375,2390 ; 4877,-1115 4877,-912.17
  text "TP1" at 305,2670 h30
  text "D1" at 155,2645 h30
  text "D5" at 440.12,2627.53 h30
  text "TP3" at 4530,2450 h30
  text "TP19" at 670,2430 h30
  text "D18" at 4380,2410 h30
  text "D7" at 736.72,2294.39 h30
  text "D14" at 3795,2280 h30
  text "D13" at 3510,2270 h30
  text "TP5" at 4140,2225 h30
  text "TP6" at 1375,2200 h30
  text "TP8" at 1660,2050 h30
  text "TP9" at 2485,1975 h30
  text "TP14" at 1045,1795 h30
  text "TP13" at 3310,1625 h30
  text "TP15" at 2575,1490 h30 r90
  text "TP12" at 3095,1490 h30 r90
  text "TP18" at 850,1470 h30 r90
  text "TP7" at 1650,1470 h30
  text "TP4" at 3180,1325 h30
  text "T1" at 435,1205 h30
  text "T2" at 3950,1190 h30
  text "TP2" at 2845,510 h30
  text "COMPONENTS MARKED 'DNP' SHOULD NOT BE POPULATED." at 1128.5,-293.5 h30
  text "ASSEMBLY VARIANT:" at 1128,-409 h30
  text ".VariantName" at 2164,-409 h30
  text "PCB VIEWED FROM TOP SIDE" at -253.5,-630.67 h30
  text "BOARD #:" at 2223,-630.67 h30
  text "TIDA-00738-Type1" at 2768.5,-630.67 h30
  text "REV:" at 3613,-630.67 h30
  text "E2" at 3904.5,-630.67 h30
  text "SVN REV:" at 4451,-630.67 h30
  text ".VersionControl_RevNumber" at 4957,-630.67 h30
  text "IGNORE ->" at 2225,-815 h30
  text "Layer Name" at -250,-830 h30
  text "=" at 105,-835 h30
  text "M5 Assembly Top" at 255,-840 h30
  text "PLOT NAME =" at -253.5,-1039.34 h30
  text ".plot_File_Name" at 552,-1039.34 h30
  text "GENERATED    :" at 2225,-1039.34 h30
  text ".Print_Date" at 3094.5,-1039.34 h30
  text ".Print_Time" at 3823.5,-1039.34 h30
  text "TEXAS INSTRUMENTS" at 5088,-1039.34 h30
M6 Assembly Bottom:
  lines w10: -317.5,-702.33 6284.5,-702.33 ; -315.5,-905.67 6284.5,-905.67 ; 1090.5,-1115.5 1090.5,-912.67 ; 1712.5,-702.33 1712.5,-499 ; 2552.5,-702.33 2552.5,-499 ; 3819.5,-1109 3819.5,-499 ; 4708.5,-1109 6284,-1109 6284,-499 -317.5,-499 -317.5,-1109 2279.5,-1109 6284.5,-1109 6284.5,-499
  text "60" at 3605,220 h30
  text "2" at 1132,210 h30
  text "1" at 1140,115 h30
  text "59" at 3605,115 h30
  text "COMPONENTS MARKED 'DNP' SHOULD NOT BE POPULATED." at 6077,-293 h30
  text ".VariantName" at 5033,-409 h30
  text "ASSEMBLY VARIANT:" at 6072,-409 h30
  text ".VersionControl_RevNumber" at 1010.5,-631.17 h30
  text "SVN REV:" at 1516.5,-631.17 h30
  text ".PCB_Rev" at 2063,-631.17 h30
  text "REV:" at 2354.5,-631.17 h30
  text "TIDA-00738-Type1" at 3199,-631.17 h30
  text "BOARD #:" at 3744.5,-631.17 h30
  text "PCB VIEWED FROM BOTTOM SIDE" at 6221,-631.17 h30
  text "M5 Assembly Bottom" at 5615,-825 h30
  text "Layer Name" at 6130,-825 h30
  text "IGNORE ->" at 2522.85,-833.49 h30
  text "=" at 5740,-835 h30
  text "TEXAS INSTRUMENTS" at 879.5,-1039.84 h30
  text ".Print_Time" at 2144,-1039.84 h30
  text ".Print_Date" at 2873,-1039.84 h30
  text "GENERATED    :" at 3742.5,-1039.84 h30
  text ".plot_File_Name" at 5415.5,-1039.84 h30
  text "PLOT NAME =" at 6221,-1039.84 h30
M9 Title Sheet:
  drawing of 57 lines, arcs and shapes, not listed
  text "1" at 714.84,8061.5 h70
  text "2" at 3210.5,8061.5 h70
  text "3" at 5699.84,8061.5 h70
  text "4" at 8206.51,8061.5 h70
  text "5" at 10705.5,8061.5 h70
  text "6" at 13210.5,8061.5 h70
  text "A" at -441.5,6918.5 h70
  text "A" at 14358.5,6918.5 h70
  text "B" at -441.5,4538.5 h70
  text "B" at 14358.5,4538.5 h70
  text "C" at -441.5,2163.5 h70
  text "C" at 14358.5,2163.5 h70
  text "PROJECT TITLE:" at 11318.5,302.5 h45
  text ".PRJ_Title" at 11368.5,169.17 h70
  text "DESIGNED FOR:" at 11318.5,1.5 h45
  text ".PRJ_Customer" at 11368.5,-138.5 h70
  text "D" at -441.5,-206.5 h70
  text "D" at 14358.5,-206.5 h70
  text "FILE NAME:" at 11318.5,-298.5 h45
  text ".PCB_File_Name_No_Path" at 11368.5,-418.5 h70
  text "Texas Instruments (TI) and/or its licensors do not warrant the accuracy or completeness of this specification" at 6349,-580.34 h45
  text "ENGINEER:" at 11318.5,-588.5 h45
  text "LAYOUT BY:" at 12823.5,-588.5 h45
  text "or any information contained therein. TI and/or its licensors do not warrant that this design will meet" at 6304.01,-693 h45
  text ".PRJ_Engineer" at 11368.5,-743.49 h70
  text ".PCB_Layout" at 12874,-743.49 h70
  text "the specifications, will be suitable for your application or fit for any particular purpose, or will operate in" at 6304.01,-805.67 h45
  text "ALTIUM DESIGNER VERSION:" at 12823.5,-898.5 h45
  text "an implementation. TI and/or its licensors do not warrant that the design is production worthy. You should" at 6304.01,-918.33 h45
  text "completely validate and test your design implementation to confirm the system functionality for your application." at 6349,-1031 h45
  text ".print_Scale" at 11368.5,-1031.83 h70
  text ".Application_BuildNumber" at 12874,-1031.83 h70
  text "1" at 714.84,-1238.5 h70
  text "2" at 3210.5,-1238.5 h70
  text "3" at 5699.84,-1238.5 h70
  text "4" at 8206.51,-1238.5 h70
  text "5" at 10705.5,-1238.5 h70
  text "6" at 13210.5,-1238.5 h70
M10 Fab Notes:
  drawing of 228 lines, arcs and shapes, not listed
  text "DESIGN INFORMATION" at 12356.02,6835 h60
  text "(REFER ALSO ARRAY/PANEL PROFILING INFORMATION)" at 11994.46,6673.29 h60
  text "BOARD SIZE" at 11308.46,6669 h60
  text "X" at 12276.46,6541.18 h60
  text "3650MIL" at 12507.78,6541.18 h60
  text "4724.41MIL" at 11720,6540 h60
  text "Number of Layers :" at 11711.46,6344 h60
  text "4" at 12806.27,6334 h60
  text "MIN. TRACK WIDTH:" at 11711.46,6205 h60
  text "8" at 12807.7,6205 h60
  text "MIL" at 12962.46,6205 h60
  text "MIN. CLEARANCE:" at 11711.46,6073 h60
  text "MIL" at 12962.46,6073 h60
  text "7" at 12800,6070 h60
  text "MIL" at 13011,5952 h60
  text "19.685" at 12668,5948 h60
  text "MIN. VIA PAD SIZE:" at 11711.46,5941 h60
  text "0.11mm (4.35MIL)" at 12406.46,5799.29 h60
  text "EXTERNAL" at 13294,5797 h60
  text "MINIMUM ANNULAR RING" at 11382.23,5795 h60
  text "PER" at 11582.23,5677 h60
  text "IPC-D-275 CLASS 2 LEVEL C" at 11802.23,5677 h60
  text "MIL, HOLES" at 13290.46,5564.71 h60
  text "+/-" at 12898,5564 h60
  text "+/-" at 13752,5564 h60
  text "REGISTRATION TOLERANCES:" at 11382.23,5559 h60
  text "METAL" at 12582,5559 h60
  text "5" at 13158.2,5559 h60
  text "3" at 13991.2,5559 h60
  text "MIL" at 14107.46,5559 h60
  text "MATERIAL:" at 11307.46,5349.54 h60
  text "FR-4 High Tg" at 12293.9,5209.21 h60
  text "FR-408" at 11728.46,5200.64 h60
  text "X" at 12140.46,5200.64 h60
  text "OTHER" at 13216.46,5200.64 h60
  text "63 MIL (1.6mm) +/-10%" at 12048.56,5037.92 h60
  text "THICKNESS:" at 11382.23,5033.64 h60
  text "X" at 11920.4,5033.64 h60
  text "OTHER" at 13333.46,5033.64 h60
  text "TOLERANCE:" at 11382.23,4875.64 h60
  text "X" at 12221.53,4875.64 h60
  text "ANSI IPC-6012 TYPE 3 CLASS 2" at 12408.48,4875.64 h60
  text "OTHER +/-" at 12408.46,4719.64 h60
  text "BOW & TWIST:" at 11382.23,4562.64 h60
  text "X" at 12221.53,4562.64 h60
  text "ANSI IPC-6012 TYPE 3 CLASS 2" at 12408.48,4562.64 h60
  text "OTHER +/-" at 12408.46,4404.13 h60
  text "COPPER THICKNESS (FINISHED):" at 11307.46,4268.64 h60
  text "1.4MIL (1oz)" at 12187.46,4115.92 h60
  text "2MIL (1.4oz)" at 12954.46,4115.92 h60
  text "2.8MIL (2oz)" at 13681.46,4115.92 h60
  text "OUTER:" at 11664.46,4111.64 h60
  text "X" at 12059,4111 h60
  text "1.4MIL (1oz)" at 12187.46,3958.92 h60
  text "2.8MIL (2oz)" at 12954.46,3958.92 h60
  text "N/A" at 13681,3959.29 h60
  text "INNER SIGNAL:" at 11375.38,3954.64 h60
  text "X" at 12060.42,3954.64 h60
  text "DRILLING:" at 11307.46,3815.64 h60
  text "REFERENCE:" at 11382.23,3698.64 h60
  text "X" at 12030.46,3698.64 h60
  text "AS SHOWN" at 12217.46,3698.64 h60
  text "X" at 12931.46,3698.64 h60
  text "NC_DRILL FILES" at 13068.46,3698.64 h60
  text "PTH MIN COPPER THICKNESS:" at 11382.23,3540.64 h60
  text "X" at 12732.46,3540.64 h60
  text "1MIL" at 12869.46,3540.64 h60
  text "OTHER" at 13366.46,3540.64 h60
  text "BOARD FINISH:" at 11307.46,3381.64 h60
  text "SILKSCREEN:" at 11462.68,3263.64 h60
  text "X" at 12411.46,3263.64 h60
  text "TOP" at 12537.46,3263.64 h60
  text "X" at 12921.46,3263.64 h60
  text "BOTTOM" at 13048.46,3263.64 h60
  text "SILKSCREEN COLOR:" at 11462.68,3096.64 h60
  text "X" at 12410.42,3096.64 h60
  text "WHITE" at 12537.46,3096.64 h60
  text "OTHER" at 13048.46,3096.64 h60
  text "SOLDER RESIST COLOR:" at 11462.68,2926.64 h60
  text "X" at 12030.42,2767.44 h60
  text "GREEN" at 12157.46,2767.44 h60
  text "BLUE" at 12748.46,2767.44 h60
  text "OTHER" at 13286.46,2767.44 h60
  text "IMMERSION GOLD (ENIG)" at 12368.46,2578.92 h60
  text "ENEPIG" at 13706,2575.64 h60
  text "SURFACE FINISH:" at 11307.46,2574.64 h60
  text "X" at 12181.51,2574.64 h60
  text "IMM. TIN/SILVER OR EQUIV" at 11637,2417.64 h60
  text "OTHER" at 13068.46,2417.64 h60
  text "ARRAY/PANEL:" at 11307.46,2238.64 h60
  text "CUT AND TRIM PER MECH LAYER 1" at 12368.46,2234.35 h60
  text "N.C. ROUTE" at 12368.46,2082.64 h60
  text "X" at 13047.46,2082.64 h60
  text "V. SCORE" at 13234.46,2082.64 h60
  text "CERTIFICATION:" at 11307.46,1945.64 h60
  text "MATERIALS AND WORKMANSHIP FOR ALL PCBS" at 12032.46,1945.64 h60
  text "TO MEET OR EXCEED THE REQUIREMENTS OF:" at 12032.46,1847.64 h60
  text "X" at 11658.96,1711.13 h60
  text "ANSI IPC-A-600F CLASS ->" at 11797.96,1711.13 h60
  text "X" at 13437.02,1711.13 h60
  text "2" at 13555.96,1711.14 h60
  text "1" at 13240.96,1709.64 h60
  text "3" at 13909.96,1709.64 h60
  text "X" at 11661.02,1551.64 h60
  text "UL 94V-0" at 11797.96,1551.64 h60
  text "X" at 12473.02,1551.64 h60
  text "RoHS" at 12609.96,1551.64 h60
  text "OTHER" at 13254.36,1551.64 h60
  text "PER ORDER" at 13651.42,1551.64 h60
  text "X" at 13336,1416 h60
  text "VIA TENTING:" at 12548,1412 h60
  text "ADDITIONAL REQUIREMENTS:" at 11307.46,1410.64 h60
  text "YES" at 13119.67,1402.92 h60
  text "NO" at 13514.47,1402.69 h60
  text "MICROSECTION:" at 11382.23,1295.64 h60
  text "YES" at 12287.96,1295.64 h60
  text "IMPEDANCE CONTROL:" at 12549,1268 h60
  text "YES" at 13569,1267 h60
  text "X" at 14127,1260 h60
  text "NO" at 13960.47,1249.69 h60
  text "REQUIRED" at 13149.46,1139.49 h60
  text "BARE BOARD ELEC. TEST:" at 11382.23,1136.64 h60
  text "NONE" at 12687.96,1136.64 h60
  text "X" at 13022.46,1136.64 h60
  text "PER ORDER" at 13741.46,1136.64 h60
  text "MANUFACTURER'S UL:" at 11382.23,979.64 h60
  text "RAIL" at 12547.96,975.35 h60
  text "METAL" at 13039.77,975.35 h60
  text "X" at 13415,975 h60
  text "SILK" at 13551.46,975.35 h60
M11 Gerber Information:
  lines w10: -317,-905.17 6283,-905.17 ; -317,-701.83 6285,-701.83 ; -317,-498.5 -317,-1108.5 3688,-1108.5 6285,-1108.5 6285,-498.5 -316.5,-498.5 -316.5,-1108.5 1259,-1108.5 ; 2148,-1108.5 2148,-498.5 ; 3415,-701.83 3415,-498.5 ; 4255,-701.83 4255,-498.5 ; 4877,-1115 4877,-912.17
  text "TIDA-00738_Type1" at 2715,-630 h40
  text "ALL ARTWORK VIEWED FROM TOP SIDE" at -253.5,-630.67 h60
  text "BOARD #:" at 2223,-630.67 h60
  text "REV:" at 3613,-630.67 h60
  text "E2" at 3904.5,-630.67 h40
  text "SVN REV:" at 4451,-630.67 h60
  text ".VersionControl_RevNumber" at 4957,-630.67 h60
  text "LAYER NAME =" at -253.5,-833.49 h60
  text "PLOT NAME =" at -253.5,-1039.34 h60
  text ".plot_File_Name" at 552,-1039.34 h60
  text "GENERATED    :" at 2225,-1039.34 h60
  text ".Print_Date" at 3094.5,-1039.34 h60
  text ".Print_Time" at 3823.5,-1039.34 h60
  text "TEXAS INSTRUMENTS" at 5088,-1039.34 h60
M12 Stackup:
  lines w6: 11340,7716.5 14198,7716.5 ; 11340,7829.1 14198,7829.1 ; 11280,7001 ccw(c11316,7001) 11316,6965 14222,6965 ccw(c14222,7001) 14258,7001 14258,7927 ccw(c14222,7927) 14222,7963 11316,7963 ccw(c11316,7927) 11280,7927 11280,7001
  text "Layer Stack Up Detail for: TIDA-00738_Type1_E2.PcbDoc" at 11340,7858.25 h51
  text "Layer" at 11340,7787.1 h26
  text "Gerber" at 12340.47,7787.1 h26
  text "Copper" at 12995.18,7787.1 h26
  text "Dielectric" at 13692.35,7787.1 h26
  text "Name" at 11340,7735.1 h26
  text "Document" at 12340.47,7735.1 h26
  text "Thickness" at 12995.18,7735.1 h26
  text "Material" at 13692.35,7735.1 h26
  text "Top Solder Mask" at 11340,7661.52 h36
  text "(.GTS)" at 12340.47,7661.52 h36
  text "Solder Resist" at 13692.35,7661.52 h36
  text "Top Layer" at 11340,7557.56 h36
  text "(.GTL)" at 12340.47,7557.56 h36
  text "1.4mil" at 12995.18,7557.56 h36
  text "FR-4 High Tg" at 13692.35,7505.58 h36
  text "GND" at 11340,7453.6 h36
  text "(.G1)" at 12340.47,7453.6 h36
  text "1.4mil" at 12995.18,7453.6 h36
  text "FR-4 High Tg" at 13692.35,7401.63 h36
  text "PWR" at 11340,7349.65 h36
  text "(.G2)" at 12340.47,7349.65 h36
  text "1.4mil" at 12995.18,7349.65 h36
  text "FR-4 High Tg" at 13692.35,7297.67 h36
  text "Bottom Layer" at 11340,7245.69 h36
  text "(.GBL)" at 12340.47,7245.69 h36
  text "1.4mil" at 12995.18,7245.69 h36
  text "Bottom Solder Mask" at 11340,7141.73 h36
  text "(.GBS)" at 12340.47,7141.73 h36
  text "Solder Resist" at 13692.35,7141.73 h36
M13 Component Bodies Top:
  text ".Layer_Name" at 552,-833.49 h60
M14 Component Bodies Bottom:
  text ".Layer_Name" at 552,-833.49 h60
M15 Courtyards Top:
  text ".Layer_Name" at 552,-833.49 h60
M16 Courtyards Bottom:
  text ".Layer_Name" at 552,-833.49 h60
Drill Drawing:
  text ".legend" at 5394,737 h60
  text "Drill Table" at 5394,622 h60
  text "FOR 7.874MIL DRILL +0/-7.874MIL" at 5399,390 h60
  text "FOR 16MIL DRILL +0/-16MIL" at 5400,286 h60
  text "FOR PTH DRILL +/-3MIL" at 5400,168 h60
  text ".Layer_Name" at 552,-833.49 h60

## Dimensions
196.85,0 to 4527,0 on M2 Board Dimensions
4724.41,3650 to 4527,0 on M2 Board Dimensions
196.85,396.7 to 196.85,0 on M2 Board Dimensions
